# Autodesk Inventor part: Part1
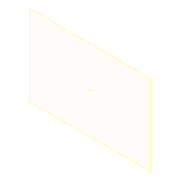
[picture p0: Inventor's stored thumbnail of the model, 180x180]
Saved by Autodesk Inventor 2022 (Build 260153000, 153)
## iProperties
Created: 2015-07
Part Number: Part1
Material: Generic
Document SubType Name: Modeling
Designer: Sandeep
Density: 1 g/cm^3
Appearance: Default
Author: Sandeep
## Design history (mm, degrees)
sketch "Sketch1"
  geometry: 1 further point
  constraints: 1 other
feature "Form1"
body "Srf1"
